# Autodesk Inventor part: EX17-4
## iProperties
Shininess: 64.0
Length Units: 11272
Angle Units: 11279
Time Units: 11290
Mass Units: 11286
Length Display Precision: 3
Compacted: True
Part Number: EX17-4
Document SubType Name: Modeling
Created: 2002-11
Designer: E. MOSS
Project: EVERGREEN VALLEY COLLEGE
Description: BUSHING
Authority: MS. TEACHER
Density: 0.0
Volumn: 0.0
Area: 0.0
PropertySet Name: Model Information
Control State: 0
Master: False
Checked Out: False
Author: E. MOSS
Revision Number: A
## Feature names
1. Extrusion1
2. Revolution1
3. Hole1
